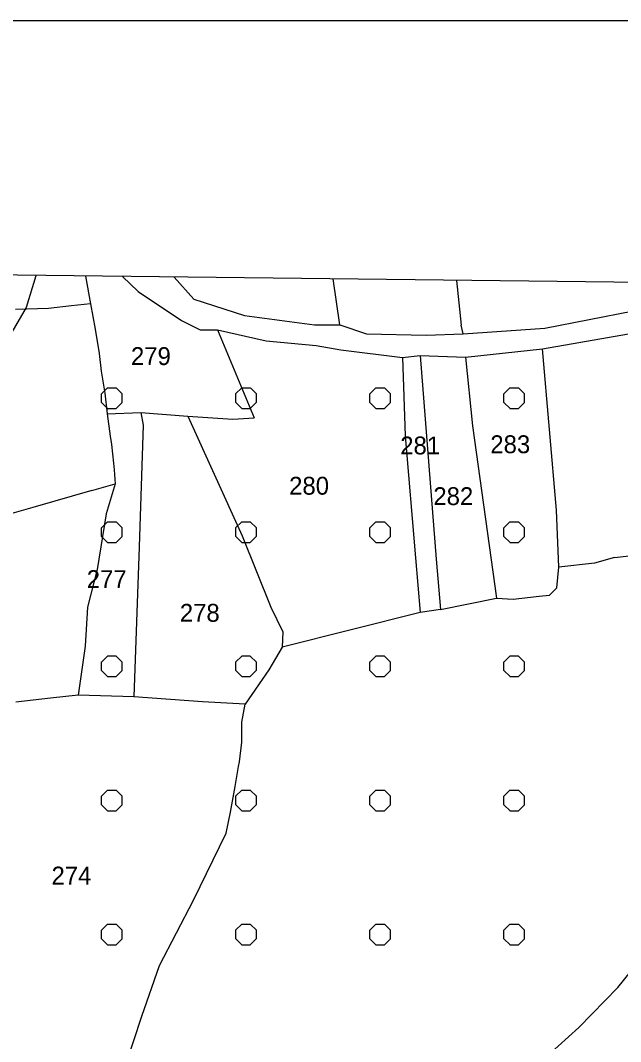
# Model space of a CAD drawing. Extents: x 410727 to 412947, y 4463506 to 4466382.
# Drawn here: x 411364.1 to 411498.4, y 4466153.2 to 4466381.6 of the extents above; entities that cross this region are included whole.
import ezdxf

# ---------------------------------------------------------------- set-up
doc = ezdxf.new("R2010")
doc.units = 0
for name, color, linetype in [('KDS_PARSEL_NO', 7, 'Continuous'), ('KDS_PL', 7, 'Continuous'), ('LJ_ÇERÇEVE', 7, 'Continuous'), ('PL_KA_TARIM_OZEL', 7, 'Continuous'), ('TR_OZELMAHSUL', 7, 'Continuous'), ('Yerlesime_uygunluk_sınırı', 7, 'Continuous')]:
    doc.layers.add(name, color=color, linetype=linetype)

msp = doc.modelspace()

# ---------------------------------------------------------------- linework, layer by layer
at = {"layer": 'KDS_PL'}
for p, q in [((411378.69, 4466324.41), (411379.82, 4466318.23)), ((411386.95, 4466324.32), (411390.49, 4466320.98)), ((411398.5, 4466324.18), (411402.9, 4466319.23)), ((411435.61, 4466313.53), (411434.11, 4466323.76)), ((411461.69, 4466323.44), (411462.75, 4466313.46)), ((411390.49, 4466320.98), (411400.19, 4466314.49)), ((411379.82, 4466318.23), (411375.54, 4466317.78)), ((411379.82, 4466318.23), (411380.83, 4466312.53)), ((411402.9, 4466319.23), (411414.25, 4466315.59)), ((411370.43, 4466317.16), (411363, 4466316.93)), ((411375.54, 4466317.78), (411370.43, 4466317.16)), ((411481.43, 4466312.75), (411501.25, 4466316.62)), ((411400.19, 4466314.49), (411404.37, 4466312.37)), ((411414.25, 4466315.59), (411429.95, 4466313.53)), ((411429.95, 4466313.53), (411435.61, 4466313.53)), ((411435.61, 4466313.53), (411441.53, 4466311.46)), ((411463.16, 4466311.46), (411462.75, 4466313.46)), ((411480.92, 4466308.11), (411523.13, 4466315.58)), ((411380.83, 4466312.53), (411381.73, 4466307.09)), ((411404.37, 4466312.37), (411408.23, 4466312.38)), ((411408.23, 4466312.38), (411416.44, 4466292.72)), ((411408.23, 4466312.38), (411419.14, 4466309.92)), ((411441.53, 4466311.46), (411454.92, 4466311.2)), ((411454.92, 4466311.2), (411463.16, 4466311.46)), ((411463.16, 4466311.46), (411481.43, 4466312.75)), ((411419.14, 4466309.92), (411430.32, 4466308.91)), ((411430.32, 4466308.91), (411435.77, 4466307.94)), ((411381.73, 4466307.09), (411382.19, 4466303.17)), ((411435.77, 4466307.94), (411449.57, 4466306.18)), ((411449.57, 4466306.18), (411453.52, 4466306.62)), ((411453.52, 4466306.62), (411457.13, 4466261.09)), ((411453.52, 4466306.62), (411463.67, 4466306.3)), ((411463.67, 4466306.3), (411480.92, 4466308.11)), ((411484.01, 4466272.04), (411480.92, 4466308.11)), ((411449.57, 4466306.18), (411450.17, 4466288.64)), ((411463.67, 4466306.3), (411465.25, 4466290.93)), ((411382.19, 4466303.17), (411383, 4466298.19)), ((411383, 4466298.19), (411383.55, 4466293.62)), ((411383.55, 4466293.62), (411391.04, 4466293.87)), ((411383.55, 4466293.62), (411384.21, 4466288.59)), ((411391.04, 4466293.87), (411401.58, 4466293.1)), ((411391.04, 4466293.87), (411391.61, 4466291.04)), ((411401.58, 4466293.1), (411411.67, 4466292.39)), ((411401.58, 4466293.1), (411413.7, 4466266.28)), ((411391.61, 4466291.04), (411390.68, 4466263.87)), ((411411.67, 4466292.39), (411416.44, 4466292.72)), ((411465.25, 4466290.93), (411470.65, 4466252.37)), ((411384.21, 4466288.59), (411384.5, 4466286.71)), ((411450.17, 4466288.64), (411452.52, 4466261.4)), ((411384.5, 4466286.71), (411384.92, 4466282.54)), ((411384.92, 4466282.54), (411385.14, 4466281.03)), ((411385.14, 4466281.03), (411385.36, 4466277.92)), ((411380.13, 4466276.4), (411385.36, 4466277.92)), ((411385.36, 4466277.92), (411383.31, 4466271.23)), ((411380.13, 4466276.4), (411367.44, 4466272.78)), ((411367.44, 4466272.78), (411360.1, 4466270.68)), ((411383.31, 4466271.23), (411381.3, 4466258.78)), ((411484.58, 4466259.29), (411484.01, 4466272.04)), ((411413.7, 4466266.28), (411420.12, 4466250.34)), ((411390.68, 4466263.87), (411389.47, 4466230.26)), ((411452.52, 4466261.4), (411453.52, 4466249.16)), ((411457.13, 4466261.09), (411458.07, 4466249.84)), ((411497.04, 4466261.47), (411492.55, 4466260.19)), ((411497.04, 4466261.47), (411504.7, 4466262.29)), ((411381.3, 4466258.78), (411379.16, 4466250.34)), ((411484.14, 4466254.69), (411484.58, 4466259.29)), ((411492.55, 4466260.19), (411484.58, 4466259.29)), ((411482.47, 4466253.01), (411484.14, 4466254.69)), ((411458.07, 4466249.84), (411470.65, 4466252.37)), ((411470.65, 4466252.37), (411474.37, 4466252.12)), ((411474.37, 4466252.12), (411480.15, 4466252.76)), ((411480.15, 4466252.76), (411482.47, 4466253.01)), ((411379.16, 4466250.34), (411378.63, 4466241.64)), ((411420.12, 4466250.34), (411422.8, 4466244.85)), ((411458.07, 4466249.84), (411453.52, 4466249.16)), ((411453.52, 4466249.16), (411422.67, 4466241.37)), ((411422.8, 4466244.85), (411422.67, 4466241.37)), ((411378.63, 4466241.64), (411377.62, 4466234.79)), ((411422.67, 4466241.37), (411419.72, 4466236.28)), ((411419.72, 4466236.28), (411414.37, 4466228.66)), ((411377.62, 4466234.79), (411377.02, 4466230.67)), ((411370.86, 4466230), (411363.1, 4466229.06)), ((411377.02, 4466230.67), (411370.86, 4466230)), ((411389.47, 4466230.26), (411377.02, 4466230.67)), ((411404.87, 4466229.19), (411389.47, 4466230.26)), ((411414.37, 4466228.66), (411404.87, 4466229.19)), ((411413.65, 4466224.61), (411414.37, 4466228.66)), ((411413.65, 4466220.1), (411413.65, 4466224.61)), ((411413.16, 4466215.71), (411413.65, 4466220.1)), ((411412.9, 4466214.7), (411413.16, 4466215.71)), ((411412.15, 4466210.19), (411412.9, 4466214.7)), ((411411.1, 4466204.49), (411412.15, 4466210.19)), ((411410.17, 4466199.75), (411411.1, 4466204.49)), ((411402.87, 4466184.78), (411410.17, 4466199.75)), ((411395.24, 4466170.16), (411402.87, 4466184.78)), ((411497.79, 4466165.25), (411503.43, 4466172.23)), ((411391.26, 4466158.85), (411395.24, 4466170.16)), ((411489.03, 4466156.27), (411497.79, 4466165.25)), ((411387.27, 4466146.55), (411391.26, 4466158.85)), ((411476.81, 4466145.32), (411489.03, 4466156.27))]:
    msp.add_line(p, q, dxfattribs=at)
at = {"layer": 'LJ_ÇERÇEVE'}
msp.add_lwpolyline([(410732.32, 4466381.6), (412946.74, 4466381.6), (412946.74, 4463506.16), (410732.32, 4463506.16)], close=True, dxfattribs=at)
at = {"layer": 'PL_KA_TARIM_OZEL'}
msp.add_lwpolyline([(411524.33, 4465912.08), (411524.97, 4465911.75), (411538.25, 4465904.8), (411538.25, 4465904.8), (411591.09, 4465931.74), (411635.3, 4465976.87), (411646.35, 4465988.84), (411652.8, 4466036.74), (411670.3, 4466088.31), (411670.3, 4466105.81), (411682.27, 4466173.05), (411679.51, 4466190.55), (411686.88, 4466263.31), (411695.17, 4466296.47), (411693.82, 4466320.72), (411344.35, 4466324.82)], dxfattribs=at)
at = {"layer": 'TR_OZELMAHSUL'}
for p, q in [((411382.28, 4466298.06), (411383.64, 4466299.41)), ((411382.29, 4466296.15), (411382.29, 4466298.07)), ((411383.64, 4466299.42), (411385.56, 4466299.42)), ((411386.92, 4466298.06), (411385.57, 4466299.41)), ((411386.91, 4466296.15), (411386.91, 4466298.07)), ((411412.28, 4466298.06), (411413.63, 4466299.41)), ((411412.29, 4466296.15), (411412.29, 4466298.07)), ((411413.64, 4466299.42), (411415.56, 4466299.42)), ((411416.92, 4466298.06), (411415.57, 4466299.41)), ((411416.91, 4466296.15), (411416.91, 4466298.07)), ((411442.28, 4466298.06), (411443.63, 4466299.41)), ((411442.29, 4466296.15), (411442.29, 4466298.07)), ((411443.64, 4466299.42), (411445.56, 4466299.42)), ((411446.92, 4466298.06), (411445.56, 4466299.41)), ((411446.91, 4466296.15), (411446.91, 4466298.07)), ((411472.28, 4466298.06), (411473.63, 4466299.41)), ((411472.29, 4466296.15), (411472.29, 4466298.07)), ((411473.64, 4466299.42), (411475.56, 4466299.42)), ((411476.92, 4466298.06), (411475.56, 4466299.41)), ((411476.91, 4466296.15), (411476.91, 4466298.07)), ((411383.65, 4466294.79), (411382.3, 4466296.14)), ((411385.55, 4466294.79), (411386.91, 4466296.14)), ((411413.65, 4466294.79), (411412.3, 4466296.14)), ((411415.55, 4466294.79), (411416.9, 4466296.14)), ((411443.65, 4466294.79), (411442.29, 4466296.14)), ((411445.55, 4466294.79), (411446.9, 4466296.14)), ((411473.65, 4466294.79), (411472.29, 4466296.14)), ((411475.55, 4466294.79), (411476.9, 4466296.14)), ((411383.64, 4466294.8), (411385.56, 4466294.8)), ((411413.64, 4466294.8), (411415.56, 4466294.8)), ((411443.64, 4466294.8), (411445.56, 4466294.8)), ((411473.64, 4466294.8), (411475.56, 4466294.8)), ((411382.28, 4466268.06), (411383.64, 4466269.41)), ((411382.29, 4466266.15), (411382.29, 4466268.07)), ((411383.64, 4466269.42), (411385.56, 4466269.42)), ((411386.92, 4466268.06), (411385.56, 4466269.41)), ((411386.91, 4466266.15), (411386.91, 4466268.07)), ((411412.28, 4466268.06), (411413.63, 4466269.41)), ((411412.29, 4466266.15), (411412.29, 4466268.07)), ((411413.64, 4466269.42), (411415.56, 4466269.42)), ((411416.92, 4466268.06), (411415.56, 4466269.41)), ((411416.91, 4466266.15), (411416.91, 4466268.07)), ((411442.28, 4466268.06), (411443.63, 4466269.41)), ((411442.29, 4466266.15), (411442.29, 4466268.07)), ((411443.64, 4466269.42), (411445.56, 4466269.42)), ((411446.92, 4466268.06), (411445.56, 4466269.41)), ((411446.91, 4466266.15), (411446.91, 4466268.07)), ((411472.28, 4466268.06), (411473.63, 4466269.41)), ((411472.29, 4466266.15), (411472.29, 4466268.07)), ((411473.64, 4466269.42), (411475.56, 4466269.42)), ((411476.92, 4466268.06), (411475.56, 4466269.41)), ((411476.91, 4466266.15), (411476.91, 4466268.07)), ((411383.65, 4466264.79), (411382.29, 4466266.14)), ((411385.55, 4466264.79), (411386.91, 4466266.14)), ((411413.65, 4466264.79), (411412.29, 4466266.14)), ((411415.55, 4466264.79), (411416.9, 4466266.14)), ((411443.65, 4466264.79), (411442.29, 4466266.14)), ((411445.55, 4466264.79), (411446.9, 4466266.14)), ((411473.65, 4466264.79), (411472.29, 4466266.14)), ((411475.55, 4466264.79), (411476.9, 4466266.14)), ((411383.64, 4466264.8), (411385.56, 4466264.8)), ((411413.64, 4466264.8), (411415.56, 4466264.8)), ((411443.64, 4466264.8), (411445.56, 4466264.8)), ((411473.64, 4466264.8), (411475.56, 4466264.8)), ((411382.28, 4466238.06), (411383.64, 4466239.41)), ((411382.29, 4466236.15), (411382.29, 4466238.07)), ((411383.64, 4466239.42), (411385.56, 4466239.42)), ((411386.92, 4466238.06), (411385.56, 4466239.41)), ((411386.91, 4466236.15), (411386.91, 4466238.07)), ((411412.28, 4466238.06), (411413.63, 4466239.41)), ((411412.29, 4466236.15), (411412.29, 4466238.07)), ((411413.64, 4466239.42), (411415.56, 4466239.42)), ((411416.92, 4466238.06), (411415.56, 4466239.41)), ((411416.91, 4466236.15), (411416.91, 4466238.07)), ((411442.28, 4466238.06), (411443.63, 4466239.41)), ((411442.29, 4466236.15), (411442.29, 4466238.07)), ((411443.64, 4466239.42), (411445.56, 4466239.42)), ((411446.92, 4466238.06), (411445.56, 4466239.41)), ((411446.91, 4466236.15), (411446.91, 4466238.07)), ((411472.28, 4466238.06), (411473.63, 4466239.41)), ((411472.29, 4466236.15), (411472.29, 4466238.07)), ((411473.64, 4466239.42), (411475.56, 4466239.42)), ((411476.92, 4466238.06), (411475.56, 4466239.41)), ((411476.91, 4466236.15), (411476.91, 4466238.07)), ((411383.65, 4466234.79), (411382.29, 4466236.14)), ((411385.55, 4466234.79), (411386.91, 4466236.14)), ((411413.65, 4466234.79), (411412.29, 4466236.14)), ((411415.55, 4466234.79), (411416.9, 4466236.14)), ((411443.65, 4466234.79), (411442.29, 4466236.14)), ((411445.55, 4466234.79), (411446.9, 4466236.14)), ((411473.65, 4466234.79), (411472.29, 4466236.14)), ((411475.55, 4466234.79), (411476.9, 4466236.14)), ((411383.64, 4466234.8), (411385.56, 4466234.8)), ((411413.64, 4466234.8), (411415.56, 4466234.8)), ((411443.64, 4466234.8), (411445.56, 4466234.8)), ((411473.64, 4466234.8), (411475.56, 4466234.8)), ((411382.28, 4466208.06), (411383.64, 4466209.42)), ((411383.64, 4466209.42), (411385.56, 4466209.42)), ((411386.92, 4466208.06), (411385.56, 4466209.41)), ((411412.28, 4466208.06), (411413.63, 4466209.41)), ((411413.64, 4466209.42), (411415.56, 4466209.42)), ((411416.92, 4466208.06), (411415.56, 4466209.41)), ((411442.28, 4466208.06), (411443.63, 4466209.41)), ((411443.64, 4466209.42), (411445.56, 4466209.42)), ((411446.92, 4466208.06), (411445.56, 4466209.41)), ((411472.28, 4466208.06), (411473.63, 4466209.41)), ((411473.64, 4466209.42), (411475.56, 4466209.42)), ((411476.92, 4466208.06), (411475.56, 4466209.41)), ((411382.29, 4466206.15), (411382.29, 4466208.07)), ((411383.65, 4466204.79), (411382.29, 4466206.14)), ((411385.55, 4466204.79), (411386.91, 4466206.15)), ((411386.91, 4466206.15), (411386.91, 4466208.07)), ((411412.29, 4466206.15), (411412.29, 4466208.07)), ((411413.65, 4466204.79), (411412.29, 4466206.14)), ((411415.55, 4466204.79), (411416.9, 4466206.14)), ((411416.91, 4466206.15), (411416.91, 4466208.07)), ((411442.29, 4466206.15), (411442.29, 4466208.07)), ((411443.65, 4466204.79), (411442.29, 4466206.14)), ((411445.55, 4466204.79), (411446.9, 4466206.14)), ((411446.91, 4466206.15), (411446.91, 4466208.07)), ((411472.29, 4466206.15), (411472.29, 4466208.07)), ((411473.65, 4466204.79), (411472.29, 4466206.14)), ((411475.55, 4466204.79), (411476.9, 4466206.14)), ((411476.91, 4466206.15), (411476.91, 4466208.07)), ((411383.64, 4466204.8), (411385.56, 4466204.8)), ((411413.64, 4466204.8), (411415.56, 4466204.8)), ((411443.64, 4466204.8), (411445.56, 4466204.8)), ((411473.64, 4466204.8), (411475.56, 4466204.8)), ((411382.28, 4466178.06), (411383.64, 4466179.42)), ((411383.64, 4466179.42), (411385.56, 4466179.42)), ((411386.92, 4466178.06), (411385.56, 4466179.41)), ((411412.28, 4466178.06), (411413.63, 4466179.41)), ((411413.64, 4466179.42), (411415.56, 4466179.42)), ((411416.92, 4466178.06), (411415.56, 4466179.41)), ((411442.28, 4466178.06), (411443.63, 4466179.41)), ((411443.64, 4466179.42), (411445.56, 4466179.42)), ((411446.92, 4466178.06), (411445.56, 4466179.41)), ((411472.28, 4466178.06), (411473.63, 4466179.41)), ((411473.64, 4466179.42), (411475.56, 4466179.42)), ((411476.92, 4466178.06), (411475.56, 4466179.41)), ((411382.29, 4466176.15), (411382.29, 4466178.07)), ((411386.91, 4466176.15), (411386.91, 4466178.07)), ((411412.29, 4466176.15), (411412.29, 4466178.07)), ((411416.91, 4466176.15), (411416.91, 4466178.07)), ((411442.29, 4466176.15), (411442.29, 4466178.07)), ((411446.91, 4466176.15), (411446.91, 4466178.07)), ((411472.29, 4466176.15), (411472.29, 4466178.07)), ((411476.91, 4466176.15), (411476.91, 4466178.07)), ((411383.65, 4466174.79), (411382.29, 4466176.14)), ((411383.64, 4466174.8), (411385.56, 4466174.8)), ((411385.55, 4466174.79), (411386.91, 4466176.15)), ((411413.65, 4466174.79), (411412.29, 4466176.14)), ((411413.64, 4466174.8), (411415.56, 4466174.8)), ((411415.55, 4466174.79), (411416.9, 4466176.14)), ((411443.65, 4466174.79), (411442.29, 4466176.14)), ((411443.64, 4466174.8), (411445.56, 4466174.8)), ((411445.55, 4466174.79), (411446.9, 4466176.14)), ((411473.65, 4466174.79), (411472.29, 4466176.14)), ((411473.64, 4466174.8), (411475.56, 4466174.8)), ((411475.55, 4466174.79), (411476.9, 4466176.14))]:
    msp.add_line(p, q, dxfattribs=at)
at = {"layer": 'Yerlesime_uygunluk_sınırı'}
msp.add_lwpolyline([(411367.59, 4466324.54), (411367.57, 4466324.45), (411365.4, 4466317.37), (411329.85, 4466256.4), (411327.98, 4466256.94), (411298.02, 4466265.64), (411235.39, 4466203.01), (411292.89, 4466117.8), (411249.96, 4466080.27), (411288.76, 4466053.15), (411335.49, 4466003.87), (411401.49, 4466010.55), (411454, 4465988), (411518.19, 4465927.25), (411576.49, 4465880.17), (411546.8, 4465853.02), (411462.76, 4465826.95), (411417.87, 4465818.6), (411360.95, 4465816.44), (411257.66, 4465822.32), (411198.74, 4465810.19), (411081.53, 4465694.24)], dxfattribs=at)

# ---------------------------------------------------------------- texts
at = {"layer": 'KDS_PARSEL_NO'}
for s, p in [('279', (411388.86, 4466304.5)), ('281', (411449.09, 4466284.51)), ('283', (411469.24, 4466284.78)), ('280', (411424.24, 4466275.5)), ('282', (411456.5, 4466273.17)), ('277', (411378.97, 4466254.61)), ('278', (411399.79, 4466247.07)), ('274', (411371.09, 4466188.29))]:
    msp.add_text(s, height=4, dxfattribs=at).set_placement(p)

doc.saveas('drawing.dxf')
